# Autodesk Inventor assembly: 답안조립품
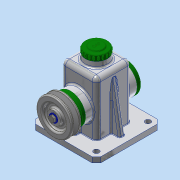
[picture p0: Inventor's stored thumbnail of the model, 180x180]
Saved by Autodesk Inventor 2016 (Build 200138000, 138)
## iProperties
Created: 2018-10
Part Number: 답안조립품
Material: 일반
Document SubType Name: Assembly
Designer: user
Author: user
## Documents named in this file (14)
- C:\Users\user\Desktop\481016V1004\답안조립품.iam
- C:\Users\user\Desktop\481016V1004\본체.ipt
- C:\Users\user\Desktop\481016V1004\베어링 15 x 35 x 11.ipt
- C:\Users\user\Desktop\481016V1004\앞커버.ipt
- C:\Users\user\Desktop\481016V1004\뒤커버.ipt
- C:\Users\user\Desktop\481016V1004\볼트 M4 x 10.ipt
- C:\Users\user\Desktop\481016V1004\상부캡.ipt
- C:\Users\user\Desktop\481016V1004\오일실 15 25 7.ipt
- C:\Users\user\Desktop\481016V1004\축.ipt
- C:\Users\user\Desktop\481016V1004\키 5 x 5 x 14.ipt
- C:\Users\user\Desktop\481016V1004\멈춤링 15 x 1.ipt
- C:\Users\user\Desktop\481016V1004\V-벨트풀리.ipt
- C:\Users\user\Desktop\481016V1004\볼트 M6 x 12.ipt
- C:\Users\user\Desktop\481016V1004\와셔.ipt
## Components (1 placed, 1 different names)
1. V-벨트풀리:1
